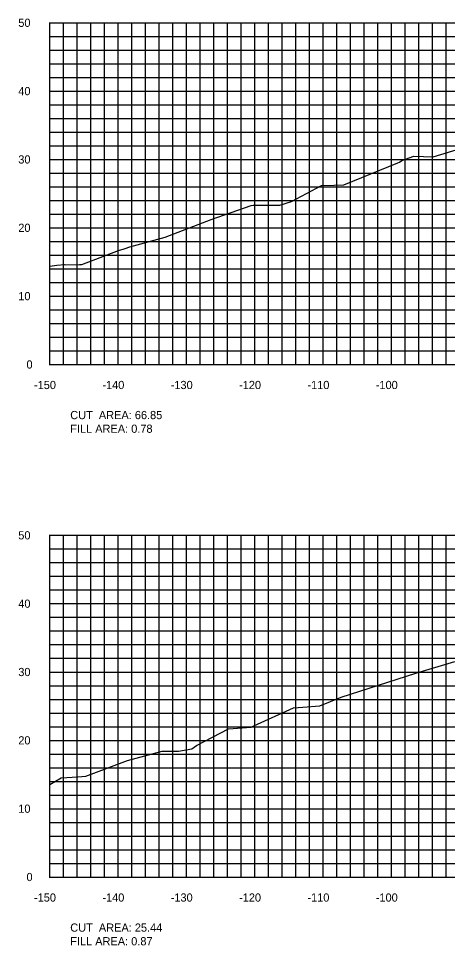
# Model space of a CAD drawing. Extents: x 1800880 to 1818864, y 245271 to 250560.
# Drawn here: x 1802136.4 to 1802199.2, y 250089.4 to 250225 of the extents above; entities that cross this region are included whole.
import ezdxf

# ---------------------------------------------------------------- set-up
doc = ezdxf.new("R2010")
doc.units = 0
for name, color, linetype in [('33', 7, 'Continuous'), ('CL-CNST', 7, 'Continuous'), ('DESIGN - DRAINAGE - Bridges', 7, 'Continuous'), ('DRAINAGETXT', 7, 'Continuous'), ('Level 46', 7, 'Continuous')]:
    doc.layers.add(name, color=color, linetype=linetype)

msp = doc.modelspace()

# ---------------------------------------------------------------- linework, layer by layer
at = {"layer": 'CL-CNST'}
for points in [[(1802141, 250188.83), (1802142.02, 250188.94), (1802143.17, 250189.07), (1802143.27, 250188.99), (1802145.35, 250189.07), (1802145.7, 250189.07), (1802151.04, 250191.09), (1802151.9, 250191.37), (1802152.05, 250191.38), (1802152.74, 250191.65), (1802153.26, 250191.8), (1802157.87, 250193.05), (1802164.63, 250195.63), (1802170.49, 250197.71), (1802170.75, 250197.73), (1802171.66, 250197.73), (1802173.08, 250197.73), (1802174.65, 250197.73), (1802176.36, 250198.28), (1802180.77, 250200.63), (1802182.6, 250200.67), (1802184.02, 250200.7), (1802191.92, 250203.93), (1802192.16, 250204.02), (1802192.52, 250204.26), (1802194.25, 250204.9), (1802197.08, 250204.79), (1802197.1, 250204.79), (1802203.95, 250206.92)], [(1802141, 250112.97), (1802142.67, 250113.94), (1802145.09, 250114.1), (1802146.26, 250114.17), (1802152.36, 250116.5), (1802157.45, 250117.87), (1802158.18, 250117.87), (1802159.85, 250117.87), (1802161.8, 250118.21), (1802162.46, 250118.66), (1802167.14, 250121.12), (1802170.46, 250121.37), (1802170.86, 250121.55), (1802176.64, 250124.17), (1802178.03, 250124.28), (1802180.53, 250124.47), (1802183.66, 250125.73), (1802194.57, 250129.25), (1802200.25, 250130.95)]]:
    msp.add_lwpolyline(points, dxfattribs=at)
at = {"layer": 'DESIGN - DRAINAGE - Bridges'}
for p, q in [((1802140.94, 250224.43), (1802141, 250224.43)), ((1802141, 250174.43), (1802141, 250224.43)), ((1802140.94, 250214.43), (1802141, 250214.43)), ((1802140.94, 250204.43), (1802141, 250204.43)), ((1802140.94, 250194.43), (1802141, 250194.43)), ((1802140.94, 250184.43), (1802141, 250184.43)), ((1802140.94, 250174.43), (1802141, 250174.43)), ((1802141, 250174.43), (1802441, 250174.43)), ((1802141, 250174.37), (1802141, 250174.43)), ((1802151, 250174.37), (1802151, 250174.43)), ((1802161, 250174.37), (1802161, 250174.43)), ((1802171, 250174.37), (1802171, 250174.43)), ((1802181, 250174.37), (1802181, 250174.43)), ((1802191, 250174.37), (1802191, 250174.43)), ((1802140.94, 250149.43), (1802141, 250149.43)), ((1802141, 250099.43), (1802141, 250149.43)), ((1802140.94, 250139.43), (1802141, 250139.43)), ((1802140.94, 250129.43), (1802141, 250129.43)), ((1802140.94, 250119.43), (1802141, 250119.43)), ((1802140.94, 250109.43), (1802141, 250109.43)), ((1802140.94, 250099.43), (1802141, 250099.43)), ((1802141, 250099.43), (1802441, 250099.43)), ((1802141, 250099.37), (1802141, 250099.43)), ((1802151, 250099.37), (1802151, 250099.43)), ((1802161, 250099.37), (1802161, 250099.43)), ((1802171, 250099.37), (1802171, 250099.43)), ((1802181, 250099.37), (1802181, 250099.43)), ((1802191, 250099.37), (1802191, 250099.43))]:
    msp.add_line(p, q, dxfattribs=at)
at = {"layer": 'Level 46'}
for p, q in [((1802141, 250224.43), (1802441, 250224.43)), ((1802141, 250174.43), (1802141, 250224.43)), ((1802143, 250174.43), (1802143, 250224.43)), ((1802145, 250174.43), (1802145, 250224.43)), ((1802147, 250174.43), (1802147, 250224.43)), ((1802149, 250174.43), (1802149, 250224.43)), ((1802151, 250174.43), (1802151, 250224.43)), ((1802153, 250174.43), (1802153, 250224.43)), ((1802155, 250174.43), (1802155, 250224.43)), ((1802157, 250174.43), (1802157, 250224.43)), ((1802159, 250174.43), (1802159, 250224.43)), ((1802161, 250174.43), (1802161, 250224.43)), ((1802163, 250174.43), (1802163, 250224.43)), ((1802165, 250174.43), (1802165, 250224.43)), ((1802167, 250174.43), (1802167, 250224.43)), ((1802169, 250174.43), (1802169, 250224.43)), ((1802171, 250174.43), (1802171, 250224.43)), ((1802173, 250174.43), (1802173, 250224.43)), ((1802175, 250174.43), (1802175, 250224.43)), ((1802177, 250174.43), (1802177, 250224.43)), ((1802179, 250174.43), (1802179, 250224.43)), ((1802181, 250174.43), (1802181, 250224.43)), ((1802183, 250174.43), (1802183, 250224.43)), ((1802185, 250174.43), (1802185, 250224.43)), ((1802187, 250174.43), (1802187, 250224.43)), ((1802189, 250174.43), (1802189, 250224.43)), ((1802191, 250174.43), (1802191, 250224.43)), ((1802193, 250174.43), (1802193, 250224.43)), ((1802195, 250174.43), (1802195, 250224.43)), ((1802197, 250174.43), (1802197, 250224.43)), ((1802199, 250174.43), (1802199, 250224.43)), ((1802141, 250222.43), (1802441, 250222.43)), ((1802141, 250220.43), (1802441, 250220.43)), ((1802141, 250218.43), (1802441, 250218.43)), ((1802141, 250216.43), (1802441, 250216.43)), ((1802141, 250214.43), (1802441, 250214.43)), ((1802141, 250212.43), (1802441, 250212.43)), ((1802141, 250210.43), (1802441, 250210.43)), ((1802141, 250208.43), (1802441, 250208.43)), ((1802141, 250206.43), (1802441, 250206.43)), ((1802141, 250204.43), (1802441, 250204.43)), ((1802141, 250202.43), (1802441, 250202.43)), ((1802141, 250200.43), (1802441, 250200.43)), ((1802141, 250198.43), (1802441, 250198.43)), ((1802141, 250196.43), (1802441, 250196.43)), ((1802141, 250194.43), (1802441, 250194.43)), ((1802141, 250192.43), (1802441, 250192.43)), ((1802141, 250190.43), (1802441, 250190.43)), ((1802141, 250188.43), (1802441, 250188.43)), ((1802141, 250186.43), (1802441, 250186.43)), ((1802141, 250184.43), (1802441, 250184.43)), ((1802141, 250182.43), (1802441, 250182.43)), ((1802141, 250180.43), (1802441, 250180.43)), ((1802141, 250178.43), (1802441, 250178.43)), ((1802141, 250176.43), (1802441, 250176.43)), ((1802141, 250174.43), (1802441, 250174.43)), ((1802141, 250149.43), (1802441, 250149.43)), ((1802141, 250099.43), (1802141, 250149.43)), ((1802143, 250099.43), (1802143, 250149.43)), ((1802145, 250099.43), (1802145, 250149.43)), ((1802147, 250099.43), (1802147, 250149.43)), ((1802149, 250099.43), (1802149, 250149.43)), ((1802151, 250099.43), (1802151, 250149.43)), ((1802153, 250099.43), (1802153, 250149.43)), ((1802155, 250099.43), (1802155, 250149.43)), ((1802157, 250099.43), (1802157, 250149.43)), ((1802159, 250099.43), (1802159, 250149.43)), ((1802161, 250099.43), (1802161, 250149.43)), ((1802163, 250099.43), (1802163, 250149.43)), ((1802165, 250099.43), (1802165, 250149.43)), ((1802167, 250099.43), (1802167, 250149.43)), ((1802169, 250099.43), (1802169, 250149.43)), ((1802171, 250099.43), (1802171, 250149.43)), ((1802173, 250099.43), (1802173, 250149.43)), ((1802175, 250099.43), (1802175, 250149.43)), ((1802177, 250099.43), (1802177, 250149.43)), ((1802179, 250099.43), (1802179, 250149.43)), ((1802181, 250099.43), (1802181, 250149.43)), ((1802183, 250099.43), (1802183, 250149.43)), ((1802185, 250099.43), (1802185, 250149.43)), ((1802187, 250099.43), (1802187, 250149.43)), ((1802189, 250099.43), (1802189, 250149.43)), ((1802191, 250099.43), (1802191, 250149.43)), ((1802193, 250099.43), (1802193, 250149.43)), ((1802195, 250099.43), (1802195, 250149.43)), ((1802197, 250099.43), (1802197, 250149.43)), ((1802199, 250099.43), (1802199, 250149.43)), ((1802141, 250147.43), (1802441, 250147.43)), ((1802141, 250145.43), (1802441, 250145.43)), ((1802141, 250143.43), (1802441, 250143.43)), ((1802141, 250141.43), (1802441, 250141.43)), ((1802141, 250139.43), (1802441, 250139.43)), ((1802141, 250137.43), (1802441, 250137.43)), ((1802141, 250135.43), (1802441, 250135.43)), ((1802141, 250133.43), (1802441, 250133.43)), ((1802141, 250131.43), (1802441, 250131.43)), ((1802141, 250129.43), (1802441, 250129.43)), ((1802141, 250127.43), (1802441, 250127.43)), ((1802141, 250125.43), (1802441, 250125.43)), ((1802141, 250123.43), (1802441, 250123.43)), ((1802141, 250121.43), (1802441, 250121.43)), ((1802141, 250119.43), (1802441, 250119.43)), ((1802141, 250117.43), (1802441, 250117.43)), ((1802141, 250115.43), (1802441, 250115.43)), ((1802141, 250113.43), (1802441, 250113.43)), ((1802141, 250111.43), (1802441, 250111.43)), ((1802141, 250109.43), (1802441, 250109.43)), ((1802141, 250107.43), (1802441, 250107.43)), ((1802141, 250105.43), (1802441, 250105.43)), ((1802141, 250103.43), (1802441, 250103.43)), ((1802141, 250101.43), (1802441, 250101.43)), ((1802141, 250099.43), (1802441, 250099.43))]:
    msp.add_line(p, q, dxfattribs=at)

# ---------------------------------------------------------------- texts
for s, p in [('-150', (1802138.7, 250170.83)), ('-140', (1802148.7, 250170.83)), ('-130', (1802158.7, 250170.83)), ('-120', (1802168.7, 250170.83)), ('-110', (1802178.7, 250170.83)), ('-100', (1802188.7, 250170.83)), ('-150', (1802138.7, 250095.83)), ('-140', (1802148.7, 250095.83)), ('-130', (1802158.7, 250095.83)), ('-120', (1802168.7, 250095.83)), ('-110', (1802178.7, 250095.83)), ('-100', (1802188.7, 250095.83))]:
    msp.add_text(s, height=1.2).set_placement(p)
at = {"layer": '33'}
for s, p in [('50', (1802136.4, 250223.83)), ('40', (1802136.4, 250213.83)), ('30', (1802136.4, 250203.83)), ('20', (1802136.4, 250193.83)), ('10', (1802136.4, 250183.83)), ('0', (1802137.6, 250173.83)), ('50', (1802136.4, 250148.83)), ('40', (1802136.4, 250138.83)), ('30', (1802136.4, 250128.83)), ('20', (1802136.4, 250118.83)), ('10', (1802136.4, 250108.83)), ('0', (1802137.6, 250098.83))]:
    msp.add_text(s, height=1.2, dxfattribs=at).set_placement(p)
at = {"layer": 'DESIGN - DRAINAGE - Bridges'}
for p in [(1802141, 250174.43), (1802141, 250099.43)]:
    msp.add_text('-', height=0.0001, dxfattribs=at).set_placement(p)
at = {"layer": 'DRAINAGETXT'}
for s, p in [('CUT  AREA: 66.85', (1802144, 250166.43)), ('FILL AREA: 0.78', (1802144, 250164.43)), ('CUT  AREA: 25.44', (1802144, 250091.43)), ('FILL AREA: 0.87', (1802144, 250089.43))]:
    msp.add_text(s, height=1.2, dxfattribs=at).set_placement(p)

doc.saveas('drawing.dxf')
